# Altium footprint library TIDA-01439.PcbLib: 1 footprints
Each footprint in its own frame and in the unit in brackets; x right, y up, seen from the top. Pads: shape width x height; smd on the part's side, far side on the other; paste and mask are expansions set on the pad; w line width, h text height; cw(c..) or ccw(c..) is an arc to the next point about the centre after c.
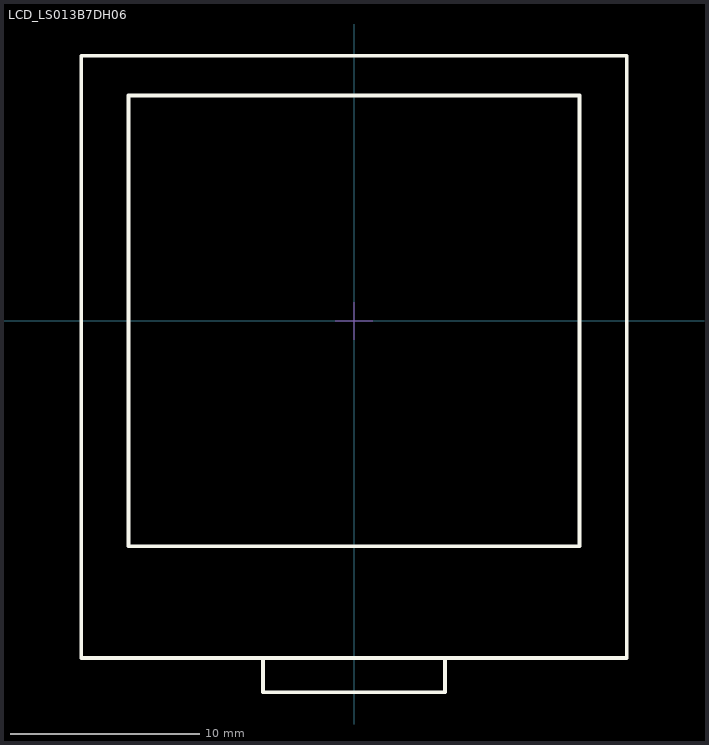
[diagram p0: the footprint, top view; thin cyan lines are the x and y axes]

## LCD_LS013B7DH06 [mm] "Outline Display"
height 1.6
Top Overlay:
  lines w0.2: -4.8,-17.8 -4.8,-19.6 4.8,-19.6 4.8,-17.8 ; -14.4,-17.8 14.4,-17.8 14.4,14 -14.4,14 -14.4,-17.8 ; -11.9,-11.9 11.9,-11.9 11.9,11.9 -11.9,11.9 -11.9,-11.9
Bottom Overlay:
  lines w0.1: -2.75,-18.8 -2.75,-14.3 ; 2.75,-18.8 2.75,-14.3 ; -2.75,-14.3 -2.75,-9.8 2.75,-9.8 2.75,-14.3 ; -2.75,-14.3 2.75,-14.3
M5 Assembly Top:
  text ".Designator" at -2,-0.7 h1.85
M15 Courtyards Top:
  lines w0.05: -1,0 0,0 ; 0,-1 0,0 ; 0,1 0,0 ; 1,0 0,0
3D body: height 0.85, standoff 0.8, extent -11.9,-11.9 11.9,11.9
3D body: height 0.8, standoff 0, extent -14.4,-17.8 14.4,14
